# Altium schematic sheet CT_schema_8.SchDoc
size 278 x 170 mm
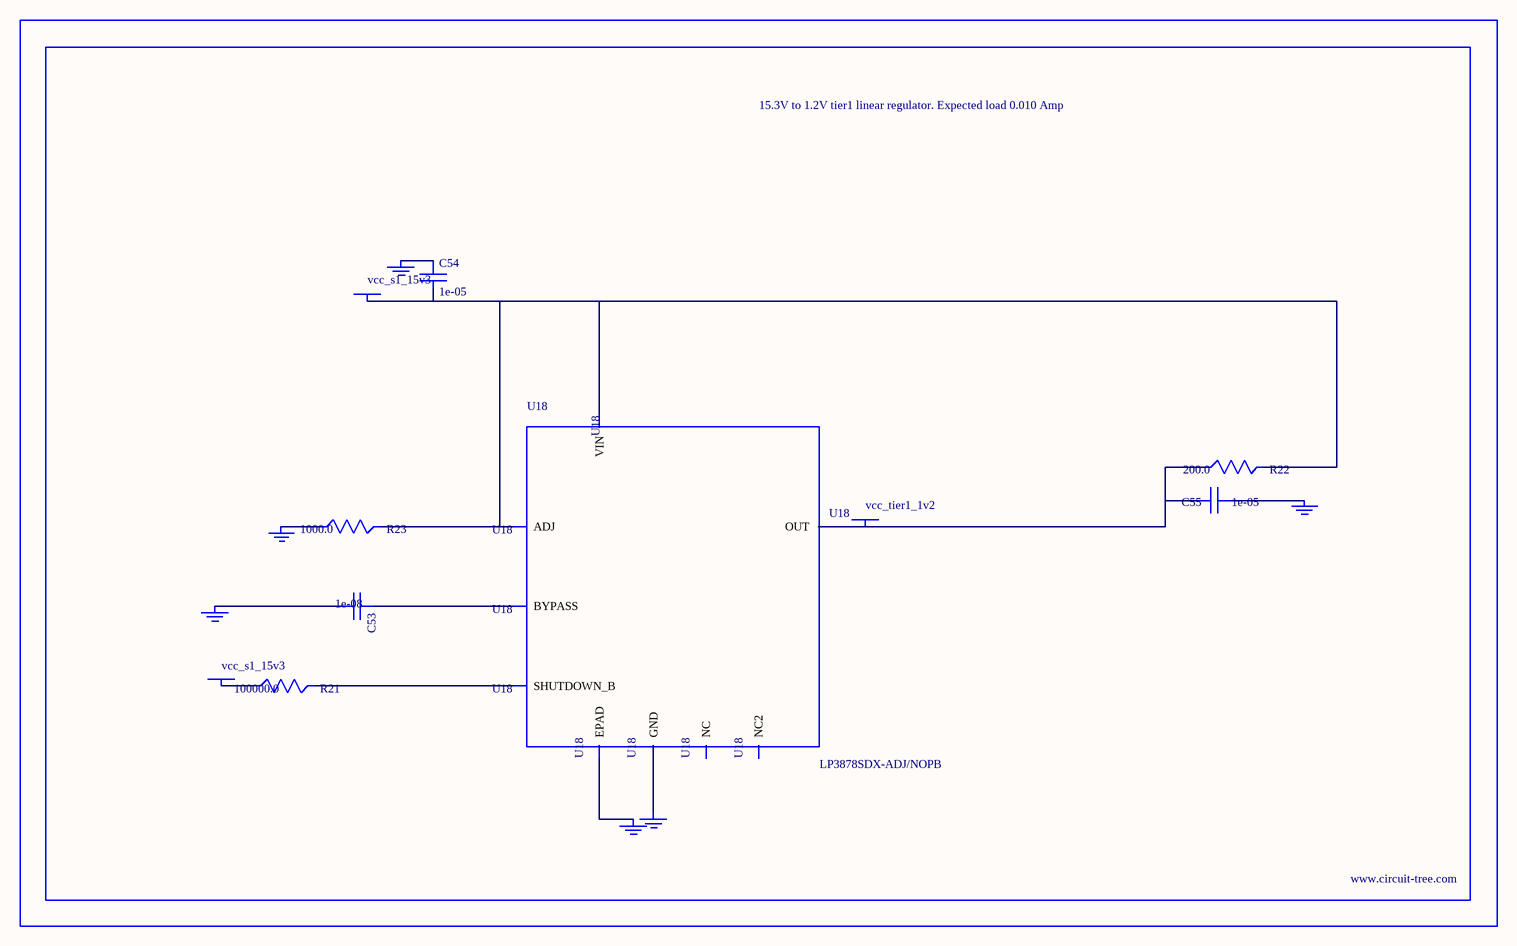
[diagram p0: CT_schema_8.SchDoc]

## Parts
BORDER7  (no value)
C53  1e-08  [C0402]
C54  1e-05  [C1210]
C55  1e-05  [C0805]
GND_INSTANCE_7_0  (no value)
GND_INSTANCE_7_1  (no value)
GND_INSTANCE_7_2  (no value)
GND_INSTANCE_7_3  (no value)
GND_INSTANCE_7_4  (no value)
GND_INSTANCE_7_5  (no value)
POWER_INSTANCE_7_0  vcc_s1_15v3
POWER_INSTANCE_7_1  vcc_s1_15v3
POWER_INSTANCE_7_2  vcc_tier1_1v2
R21  100000.0  [R0603]
R22  200.0  [R0603]
R23  1000.0  [R0603]
U18  LP3878SDX-ADJ/NOPB  [WSON-8]

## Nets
NetC53_1: C53.1 U18.1(BYPASS)
NetC53_2: C53.2 GND_INSTANCE_7_0.0(GND)
NetC54_1: C54.1 GND_INSTANCE_7_1.0(GND)
NetC54_2: C54.2 POWER_INSTANCE_7_0.0(PWR) R22.2 R23.2 U18.4(VIN) U18.6(ADJ)
NetC55_1: C55.1 GND_INSTANCE_7_2.0(GND)
NetC55_2: C55.2 POWER_INSTANCE_7_2.0(PWR) R22.1 U18.5(OUT)
NetGND_INSTANCE_7_3_0: GND_INSTANCE_7_3.0(GND) R23.1
NetGND_INSTANCE_7_4_0: GND_INSTANCE_7_4.0(GND) U18.PAD(EPAD)
NetGND_INSTANCE_7_5_0: GND_INSTANCE_7_5.0(GND) U18.3(GND)
NetPOWER_INSTANCE_7_1_0: POWER_INSTANCE_7_1.0(PWR) R21.1
NetR21_2: R21.2 U18.8(SHUTDOWN_B)

Not connected (* = marked no-connect by the designer): U18 2(NC) 7(NC2)

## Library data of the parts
BORDER7 = BORDER_PAGE7
C53 = C0402C103K3RAC
C54 = C1210C106K5PACTU
C55 = GRM219R60J106ME19D
GND_INSTANCE_7_0-GND_INSTANCE_7_5 = GND
POWER_INSTANCE_7_0-POWER_INSTANCE_7_2 = PWR
R21 = RC0603JR-07100KL
R22 = RC0603JR-07200RL
R23 = RC0603JR-071KL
